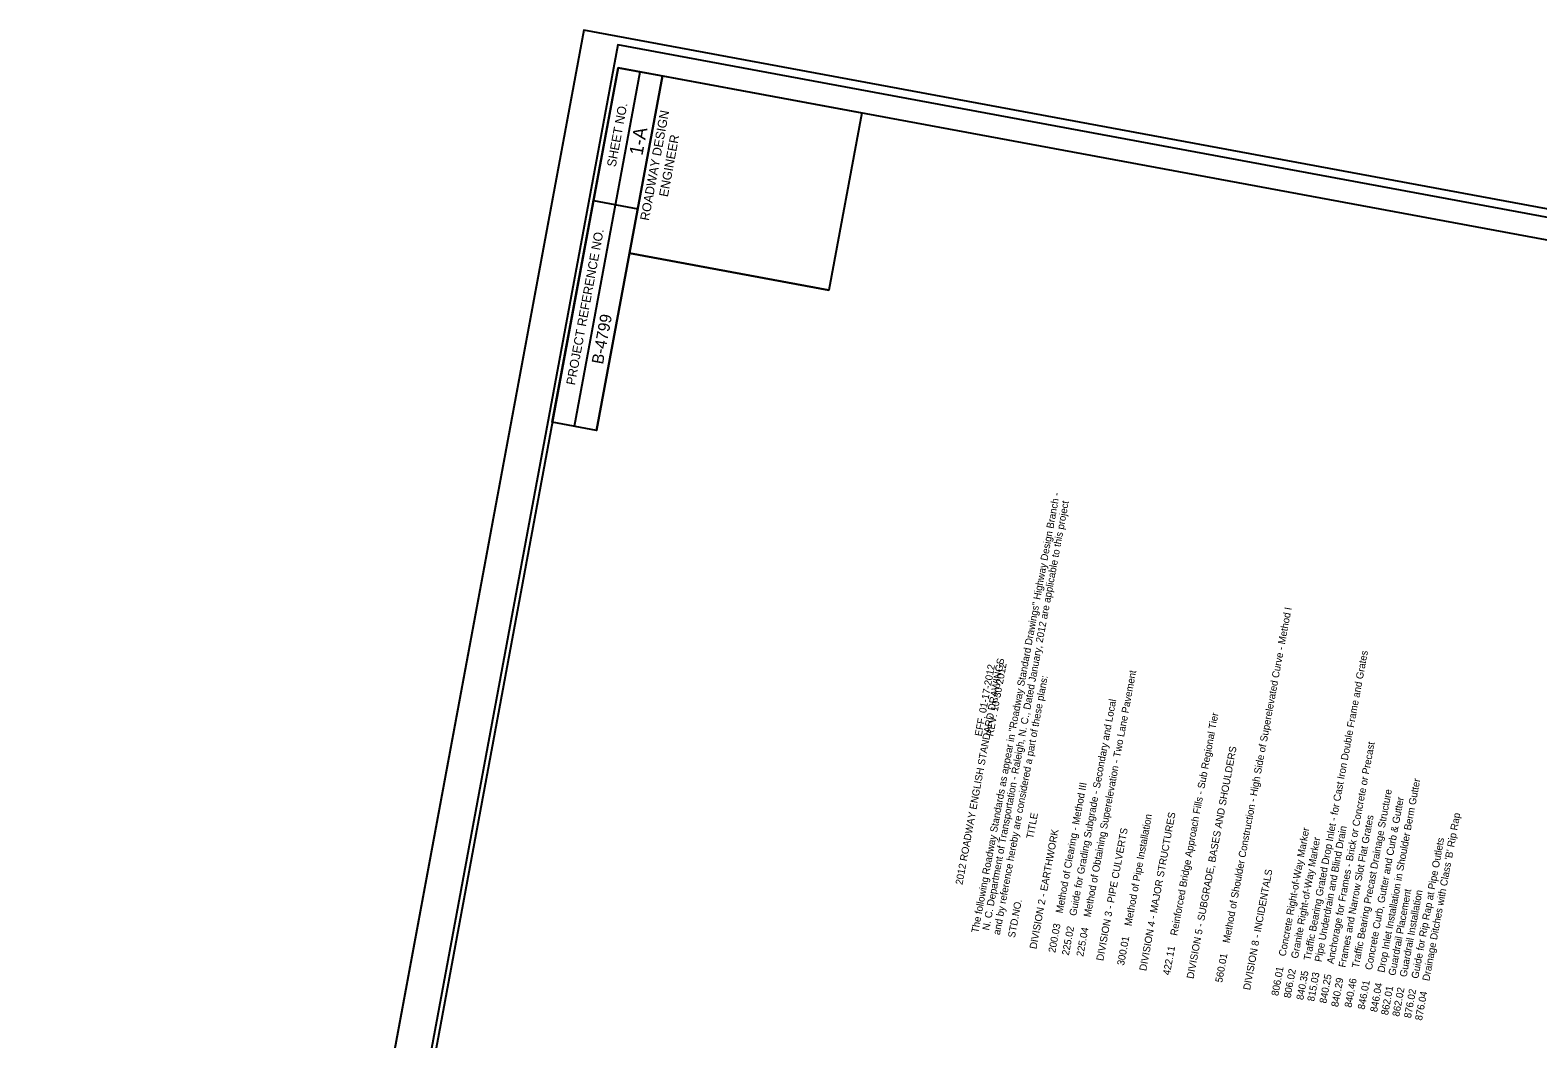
# Model space of a CAD drawing. Extents: x 1665923 to 1668724, y 690926 to 694920.
# Drawn here: x 1667341 to 1668177, y 694361 to 694920 of the extents above; entities that cross this region are included whole.
import ezdxf

# ---------------------------------------------------------------- set-up
doc = ezdxf.new("R2010")
doc.units = 0
for name, color, linetype in [('Default', 7, 'Continuous'), ('Sheet Cutting Line CELL', 7, 'Continuous'), ('Sheet Data Field CELL', 7, 'Continuous'), ('Sheet Plan CELL', 7, 'Continuous'), ('Sheet Plot Border Inside CELL', 7, 'Continuous'), ('Sheet Plot Border Outside CELL', 7, 'Continuous')]:
    doc.layers.add(name, color=color, linetype=linetype)

msp = doc.modelspace()

# ---------------------------------------------------------------- linework, layer by layer
at = {"layer": 'Sheet Cutting Line CELL'}
msp.add_line((1667647.87, 694920.43), (1667340.61, 693265.21), dxfattribs=at)
at = {"layer": 'Sheet Plan CELL'}
for p, q in [((1667642.72, 694700.63), (1667679.23, 694897.32)), ((1667655.01, 694698.35), (1667691.52, 694895.04)), ((1667655.01, 694698.35), (1667691.52, 694895.04)), ((1667653.25, 694825.86), (1667677.83, 694821.3)), ((1667673.27, 694796.72), (1667783.83, 694776.2))]:
    msp.add_line(p, q, dxfattribs=at)
for points in [[(1667666.89, 694899.61), (1667393.12, 693424.81), (1668425.49, 693233.17), (1668699.25, 694707.98)], [(1667630.38, 694702.92), (1667666.89, 694899.61), (1667691.52, 694895.04), (1667655.01, 694698.35)], [(1667673.27, 694796.72), (1667691.52, 694895.04), (1667802.13, 694874.51), (1667783.88, 694776.19)]]:
    msp.add_lwpolyline(points, close=True, dxfattribs=at)
at = {"layer": 'Sheet Plot Border Inside CELL'}
msp.add_lwpolyline([(1668399.93, 693081.79), (1668703.99, 694719.81), (1667666.71, 694912.36), (1667362.65, 693274.34)], close=True, dxfattribs=at)
at = {"layer": 'Sheet Plot Border Outside CELL'}
msp.add_lwpolyline([(1668417.22, 693065.36), (1668724.48, 694720.58), (1667647.87, 694920.43), (1667340.61, 693265.21)], close=True, dxfattribs=at)

# ---------------------------------------------------------------- texts
at = {"layer": 'Default'}
for s, p in [('The following Roadway Standards as appear in "Roadway Standard Drawings" Highway Design Branch -', (1667866.82, 694419.13)), ('N. C. Department of Transportation - Raleigh, N. C., Dated January, 2012 are applicable to this project', (1667872.92, 694420.61)), ('560.01    Method of Shoulder Construction - High Side of Superelevated Curve - Method I', (1668002.19, 694391.66)), ('2012 ROADWAY ENGLISH STANDARD DRAWINGS', (1667858.02, 694445.88)), ('840.35    Traffic Bearing Grated Drop Inlet - for Cast Iron Double Frame and Grates', (1668047.18, 694381.98)), ('                                                      EFF. 01-17-2012', (1667854.07, 694449.43)), ('                                                      REV. 10-30-2012', (1667860.43, 694449.43)), ('and by reference hereby are considered a part of these plans:', (1667878.8, 694418.12)), ('225.04    Method of Obtaining Superelevation - Two Lane Pavement', (1667925.08, 694406.06)), ('225.02    Guide for Grading Subgrade - Secondary and Local', (1667917.08, 694406.73)), ('422.11    Reinforced Bridge Approach Fills - Sub Regional Tier', (1667973.14, 694395.75)), ('DIVISION 5 - SUBGRADE, BASES AND SHOULDERS', (1667986.31, 694393.73)), ('840.25    Anchorage for Frames - Brick or Concrete or Precast', (1668060, 694380.09)), ('846.04    Drop Inlet Installation in Shoulder Berm Gutter', (1668088.16, 694375.26)), ('200.03    Method of Clearing - Method III', (1667909.56, 694408.19)), ('840.46    Traffic Bearing Precast Drainage Structure', (1668073.94, 694377.79)), ('846.01    Concrete Curb, Gutter and Curb & Gutter', (1668081.22, 694376.69)), ('DIVISION 4 - MAJOR STRUCTURES', (1667960.02, 694398.1)), ('STD.NO.                       TITLE', (1667887.12, 694416.48)), ('300.01    Method of Pipe Installation ', (1667947.71, 694401.12)), ('806.01    Concrete Right-of-Way Marker', (1668033.33, 694384.28)), ('815.03    Pipe Underdrain and Blind Drain', (1668053.26, 694381.16)), ('840.29    Frames and Narrow Slot Flat Grates', (1668066.55, 694378.09)), ("876.04    Drainage Ditches with Class 'B' Rip Rap", (1668113.07, 694370.59)), ('DIVISION 2 - EARTHWORK', (1667899.1, 694410.25)), ('DIVISION 3 - PIPE CULVERTS', (1667936.16, 694403.68)), ('806.02    Granite Right-of-Way Marker', (1668040.16, 694383.06)), ('876.02    Guide for Rip Rap at Pipe Outlets', (1668106.94, 694371.91)), ('DIVISION 8 - INCIDENTALS', (1668017.68, 694387.47)), ('862.01    Guardrail Placement', (1668094.22, 694373.56)), ('862.02    Guardrail Installation', (1668100.45, 694372.77))]:
    msp.add_text(s, height=4, rotation=79.48395, dxfattribs=at).set_placement(p)
at = {"layer": 'Sheet Data Field CELL'}
for s, height, p in [('1-A', 7.5, (1667680.4, 694850.5)), ('B-4799', 6.48, (1667658.52, 694734.69))]:
    msp.add_text(s, height=height, rotation=79.48395, dxfattribs=at).set_placement(p)
at = {"layer": 'Sheet Plan CELL'}
for s, height, p in [('SHEET NO.', 5, (1667665.56, 694844.23)), ('ROADWAY DESIGN', 5.0001, (1667683.99, 694814.46)), ('ENGINEER', 5, (1667694.51, 694827.61)), ('PROJECT REFERENCE NO.', 5.0001, (1667642.98, 694723.16))]:
    msp.add_text(s, height=height, rotation=79.48395, dxfattribs=at).set_placement(p)

doc.saveas('drawing.dxf')
